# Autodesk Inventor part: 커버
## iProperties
Company: 한국ATC센터
Created: 2014-10
Part Number: 커버
Document SubType Name: Modeling
Designer: 한국ATC센터
Density: 2.71 g/cm^3
Material: 알루미늄-6061
Mass: 189.975 g
Surface Area: 197.126 cm^2
Volume: 70.1013 cm^3
Author: KYOUNG IL JANG
